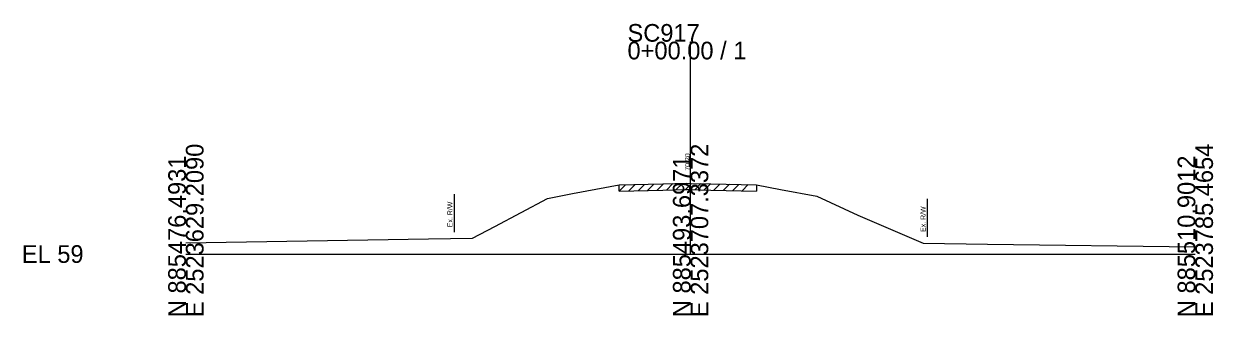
# Model space of a CAD drawing. Extents: x -26 to 218, y -10 to 12021.
# Drawn here: x -25.7 to 162.8, y -9.7 to 36.5 of the extents above; entities that cross this region are included whole.
import ezdxf

# ---------------------------------------------------------------- set-up
doc = ezdxf.new("R2010")
doc.units = 0
for name, color, linetype in [('RD_GPK_XS_Cell', 7, 'Continuous'), ('RD_XS_ExGround', 7, 'Continuous'), ('RD_XS_ExPaveRet', 7, 'Continuous'), ('RD_XS_ExRW', 7, 'Continuous'), ('RD_XS_TX_Elev_EX', 7, 'Continuous')]:
    doc.layers.add(name, color=color, linetype=linetype)

msp = doc.modelspace()

# ---------------------------------------------------------------- linework, layer by layer
at = {"layer": 'RD_GPK_XS_Cell'}
for p, q in [((80, 0), (80, 33.64)), ((0, 0), (80, 0)), ((80, 0), (160, 0))]:
    msp.add_line(p, q, dxfattribs=at)
at = {"layer": 'RD_XS_ExGround'}
for p, q in [((57.33, 8.8), (61.27, 9.59)), ((61.27, 9.59), (68.67, 10.94)), ((68.67, 10.94), (75.6, 11.11)), ((75.6, 11.11), (79.33, 11.21)), ((79.33, 11.21), (80, 11.2)), ((80, 11.2), (83.21, 11.13)), ((83.21, 11.13), (90.45, 10.96)), ((90.45, 10.96), (94.26, 10.23)), ((94.26, 10.23), (99.99, 9.15)), ((48.98, 4.37), (57.33, 8.8)), ((99.99, 9.15), (106.53, 6.18)), ((106.53, 6.18), (116.85, 1.73)), ((45.41, 2.49), (48.98, 4.37)), ((0, 1.76), (38.46, 2.42)), ((38.46, 2.42), (45.41, 2.49)), ((116.85, 1.73), (127.06, 1.54)), ((127.06, 1.54), (160, 1.16))]:
    msp.add_line(p, q, dxfattribs=at)
at = {"layer": 'RD_XS_ExPaveRet'}
for p, q in [((68.67, 9.94), (69.7, 10.96)), ((68.67, 9.94), (68.67, 10.94)), ((68.67, 9.94), (75.6, 10.11)), ((70.17, 9.98), (71.2, 11)), ((71.67, 10.01), (72.7, 11.04)), ((73.17, 10.05), (74.2, 11.08)), ((74.67, 10.09), (75.7, 11.11)), ((75.6, 10.11), (79.33, 10.21)), ((76.17, 10.13), (77.2, 11.16)), ((77.67, 10.17), (78.7, 11.2)), ((79.17, 10.21), (80.16, 11.19)), ((79.33, 10.21), (80, 10.2)), ((80, 10.2), (83.21, 10.13)), ((80.67, 10.18), (81.65, 11.16)), ((82.17, 10.15), (83.15, 11.13)), ((83.21, 10.13), (90.45, 9.96)), ((83.67, 10.12), (84.65, 11.09)), ((85.17, 10.08), (86.15, 11.06)), ((86.67, 10.05), (87.65, 11.03)), ((88.17, 10.02), (89.15, 10.99)), ((90.45, 10.96), (90.45, 9.96))]:
    msp.add_line(p, q, dxfattribs=at)
at = {"layer": 'RD_XS_ExRW'}
for p, q in [((42.5, 9.46), (42.5, 3.46)), ((117.5, 8.72), (117.5, 2.72))]:
    msp.add_line(p, q, dxfattribs=at)

# ---------------------------------------------------------------- texts
at = {"layer": 'RD_GPK_XS_Cell'}
for s, p in [('SC917', (70, 33.64)), ('0+00.00 / 1', (70, 30.84)), ('EL 59', (-26, -1.4))]:
    msp.add_text(s, height=2.8, dxfattribs=at).set_placement(p)
for s, p in [('E 2523629.2090', (2.8, -10)), ('E 2523707.3372', (82.8, -10)), ('E 2523785.4654', (162.8, -10)), ('N 885476.4931', (0, -10)), ('N 885493.6971', (80, -10)), ('N 885510.9012', (160, -10))]:
    msp.add_text(s, height=2.8, rotation=90, dxfattribs=at).set_placement(p)
at = {"layer": 'RD_XS_ExRW'}
for p in [(42.25, 4.25), (117.25, 3.5)]:
    msp.add_text('Ex. R/W ', height=0.8, rotation=90, dxfattribs=at).set_placement(p)
at = {"layer": 'RD_XS_TX_Elev_EX'}
msp.add_text('70.20', height=0.8, rotation=90, dxfattribs=at).set_placement((79.9, 13.2))

doc.saveas('drawing.dxf')
